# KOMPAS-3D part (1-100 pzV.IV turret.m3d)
File: created 05.08.2017 10:06:16, last saved 05.08.2017 10:38:09.
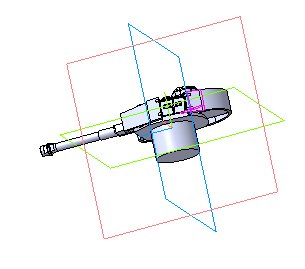
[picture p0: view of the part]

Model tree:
1. Операция без истории:1
2. Эскиз:1
3. Операция выдавливания:1
     Расстояние 1 = 0.4
4. Эскиз:2
5. Операция выдавливания:2
     Расстояние 1 = 0.2
6. Операция выдавливания:3
     Расстояние 1 = 0.4
7. Эскиз:3
8. Вырезать элемент выдавливания:1
     Расстояние 1 = 10.8
9. Эскиз:4
10. Операция выдавливания:4
     Расстояние 1 = 0.2
11. Операция выдавливания:5
     Расстояние 1 = 0.5
12. Эскиз:5
13. Вырезать элемент выдавливания:2
     Расстояние 1 = 10.8
14. Эскиз:6
15. Эскиз:7
16. Вырезать элемент выдавливания:3
     Расстояние 2 = 0.4; Расстояние 1 = 0.4
17. Эскиз:8
18. Операция выдавливания:7
     Расстояние 1 = 0.4
19. Эскиз:9
20. Вырезать элемент выдавливания:4
     Расстояние 2 = 0.4; Расстояние 1 = 0.4
21. Эскиз:10
22. Вырезать элемент выдавливания:5
     Расстояние 2 = 0.4; Расстояние 1 = 10.4
23. Вырезать элемент выдавливания:6
     Расстояние 2 = 0.4; Расстояние 1 = 0.4
24. Вырезать элемент выдавливания:7
     Расстояние 2 = 0.4; Расстояние 1 = 0.4
25. Вырезать элемент выдавливания:8
     Расстояние 2 = 0.4; Расстояние 1 = 0.4
26. Эскиз:11
27. Вырезать элемент выдавливания:9
     Расстояние 2 = 0.4; Расстояние 1 = 10.4
28. Эскиз:12
29. Операция выдавливания:9
     Расстояние 1 = 0.4
30. Операция выдавливания:10
     Расстояние 1 = 0.4
31. Операция выдавливания:11
     Расстояние 1 = 0.4
32. Операция выдавливания:12
     Расстояние 1 = 0.6
33. Операция выдавливания:13
     Расстояние 1 = 0.6
34. Эскиз:13
35. Операция выдавливания:14
     Расстояние 1 = 0.4
36. Эскиз:14
37. Вырезать элемент выдавливания:10
     Расстояние 1 = 0.4
38. Эскиз:15
39. Операция выдавливания:15
     Расстояние 1 = 0.4
40. Эскиз:16
41. Вырезать элемент выдавливания:11
     Расстояние 1 = 0.4
42. Эскиз:17
43. Эскиз:18
44. Операция выдавливания:16
     Расстояние 1 = 0.2
45. Операция выдавливания:17
     Расстояние 1 = 0.35
46. Операция выдавливания:18
     Расстояние 1 = 0.35
47. Эскиз:19
48. Вырезать элемент выдавливания:14
     Расстояние 1 = 10.4
49. Эскиз:20
50. Вырезать элемент выдавливания:15
     Расстояние 1 = 10.4
51. Вырезать элемент выдавливания:16
     Расстояние 1 = 10.4
52. Операция выдавливания:19
     Расстояние 1 = 0.4
53. Операция выдавливания:20
     Расстояние 1 = 0.4
54. Операция выдавливания:21
     Расстояние 1 = 0.4
55. Операция выдавливания:22
     Расстояние 1 = 0.6
56. Операция выдавливания:23
     Расстояние 1 = 0.6
57. Эскиз:21
58. Операция выдавливания:24
     Расстояние 1 = 0.6; Расстояние 2 = 0.6
59. Эскиз:22
60. Операция выдавливания:25
     Расстояние 1 = 0.6; Расстояние 2 = 0.6
61. Эскиз:23
62. Операция выдавливания:26
     Расстояние 1 = 0.6; Расстояние 2 = 0.6
63. Эскиз:24
64. Операция выдавливания:27
     Расстояние 1 = 0.6; Расстояние 2 = 0.6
